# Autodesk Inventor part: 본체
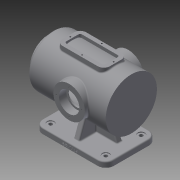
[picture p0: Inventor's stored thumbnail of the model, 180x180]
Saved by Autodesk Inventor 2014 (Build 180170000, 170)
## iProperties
Created: 2021-11
Part Number: 본체
Material: Generic
Document SubType Name: Modeling
Designer: kb542
Density: 1 g/cm^3
Appearance: Default
Author: kb542
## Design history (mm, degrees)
sketch "스케치1"
  geometry: L1 (0, 0)-(210, 0); L2 (0, 32.5)-(0, 47.5); L3 (0, 47.5)-(10, 47.5); L4 (10, 47.5)-(10, 65); L5 (10, 65)-(210, 65); L6 (210, 65)-(210, 0); L7 (0, 32.5)-(25, 32.5); L8 (25, 32.5)-(25, 55); L9 (25, 55)-(200, 55); L10 (200, 55)-(200, 0)
  constraints: 20 end point, 5 perpendicular, 3 parallel, 2 horizontal, 1 point on line, 1 vertical alignment
  dimensions: "d0" = 10 distance between parallel lines of L6 L10; "d1" = 210 distance of L1.start L1.end; "d2" = 25 distance of L2.start L7.end; "d3" = 10 distance of L2.end L3.end; "d4" = 65 diameter of L7 L1; "d5" = 95 diameter of L3 L1; "d6" = 130 diameter of L5 L1; "d7" = 110 diameter of L9 L1
revolve "회전1" sketch "스케치1" stored, may be unused: angle "d8" = 90 deg
node "작업 평면1"
sketch "스케치2"
  geometry: L1 (50, 65)-(190, 65); L2 (210, 45)-(210, -45); L3 (190, -65)-(50, -65); L4 (30, -45)-(30, 45); L5 (0, -47.5)-(0, 47.5) reference; A1 r 20 centre (50, 45) between (50, 65) and (30, 45); A2 r 20 centre (190, 45) between (210, 45) and (190, 65); A3 r 20 centre (190, -45) between (190, -65) and (210, -45); A4 r 20 centre (50, -45) between (30, -45) and (50, -65); 6 further points
  constraints: 8 end point, 8 point on circle, 8 tangent, 6 point on line, 4 centre point, 3 equal radius, 2 midpoint, 2 parallel, 1 horizontal, 1 horizontal alignment, 1 perpendicular
  dimensions: "d10" = 180 distance of point (30, 65) point (210, 65); "d11" = 130 distance of point (30, -65) point (30, 65); "d12" = 30 distance between parallel lines of L4 L5; "d13" = 20 radius of A1
extrude "돌출1" join sketch "스케치2" distance "d14" = 14; taper "d15" = 0 deg
sketch "스케치3"
  geometry: A1 r 20 centre (50, 45) between (50, 65) and (30, 45) reference; A2 r 20 centre (50, -45) between (30, -45) and (50, -65) reference; A3 r 20 centre (190, -45) between (190, -65) and (210, -45) reference; A4 r 20 centre (190, 45) between (210, 45) and (190, 65) reference; 5 further points
  constraints: 4 coincident
hole "구멍1" sketch "스케치3" at (50, 45), (190, 45), (190, -45), (50, -45) diameter "d16" = 9; stored, may be unused: countersink angle "d20" = 90 deg, drill point angle "d22" = 118 deg; dims "d17" = 6, "d18" = 18, "d19" = 2, "d21" = 8
node "작업 평면2"
sketch "스케치4"
  geometry: L1 (65, 30)-(155, 30); L2 (170, 15)-(170, -15); L3 (155, -30)-(65, -30); L4 (50, -15)-(50, 15); L5 (0, -47.5)-(0, 47.5) reference; L6 (155, 20)-(65, 20); L7 (60, 15)-(60, -15); L8 (65, -20)-(155, -20); L9 (160, -15)-(160, 15); A1 r 15 centre (65, 15) between (65, 30) and (50, 15); A2 r 15 centre (65, -15) between (50, -15) and (65, -30); A3 r 15 centre (155, -15) between (155, -30) and (170, -15); A4 r 15 centre (155, 15) between (170, 15) and (155, 30); A5 r 5 centre (65, 15) between (65, 20) and (60, 15); A6 r 5 centre (65, -15) between (60, -15) and (65, -20); A7 r 5 centre (155, -15) between (155, -20) and (160, -15); A8 r 5 centre (155, 15) between (160, 15) and (155, 20); 6 further points
  constraints: 16 end point, 16 point on circle, 8 centre point, 8 tangent, 6 point on line, 4 parallel, 3 equal radius, 2 midpoint, 2 perpendicular, 1 horizontal, 1 horizontal alignment, 7 other
  dimensions: "d24" = 120 distance of point (50, 30) point (170, 30); "d25" = 60 distance of point (50, -30) point (50, 30); "d26" = 50 distance between parallel lines of L5 L4; "d27" = 15 radius of A1; "d28" = 10 distance between parallel lines of L6 L1
extrude "돌출2" join sketch "스케치4" stored distance "d29" = 140; taper "d30" = 0 deg
node "작업 평면3"
sketch "스케치5"
  geometry: L1 (-14, 90)-(-14, 0) reference; L2 (-14, -9)-(-14, 9) reference; L3 (-14, 81)-(-14, 99) reference; L4 (-14, 110)-(-14, 90) reference; L5 (-14, 0)-(-14, -20) reference; L6 (-58.485, 11.191)-(-14, -5); L7 (-58.485, 78.809)-(-14, 95); L8 (-114, 45)-(-49, 45); A1 r 65 centre (-114, 45) between (-58.485, 11.191) and (-58.485, 78.809) reference; 1 further point
  constraints: 6 end point, 3 point on circle, 2 point on line, 1 perpendicular, 1 other
  dimensions: "d31" = 110 deg angle of L5 L6; "d32" = 100 distance of L7.end L6.end
extrude "돌출3" join sketch "스케치5" stored distance "d33" = 14; taper "d34" = 0 deg
node "작업 평면4"
sketch "스케치6"
  geometry: L1 (18.887, 38.416)-(10, 14); L2 (118.776, 44.837)-(130, 14); L3 (140, 14)-(0, 14) reference; L4 (0, 0)-(140, 0) reference; L5 (70, 14)-(70, 0); 1 further point
  constraints: 6 end point, 2 midpoint, 2 point on line, 1 other
  dimensions: "d35" = 110 deg angle of L3 L1; "d37" = 120 distance of L2.end L1.end
feature "리브1" dims "d38" = 1, "d39" = 14, "d40" = 0, "d41" = 0, "d42" = 1, "d43" = 1
feature "리브2" dims "d44" = 1, "d45" = 14, "d46" = 0, "d47" = 0, "d48" = 1, "d49" = 1
node "작업 평면5"
sketch "스케치8"
  geometry: L1 (0, -47.5)-(0, 47.5) reference; C1 r 40 at (127, 0); 2 further points
  constraints: 1 centre point, 1 horizontal alignment, 1 midpoint
  dimensions: "d51" = 127 distance from line of C1.centre L1; "d52" = 80 diameter of C1
extrude "돌출4" join sketch "스케치8" stored distance "d53" = 14; taper "d54" = 0 deg
sketch "스케치9"
  geometry: C1 r 40 at (0, 0) reference; 2 further points
  constraints: 1 coincident
hole "구멍2" sketch "스케치9" at (0, 0) diameter "d55" = 42; stored, may be unused: countersink angle "d59" = 90 deg, drill point angle "d61" = 118 deg; dims "d56" = 6, "d57" = 52, "d58" = 19, "d60" = 8
sketch "스케치10"
  geometry: C1 r 40 at (0, 0) reference; A1 r 32.5 centre (0, 0) between (0, 32.5) and (-32.5, 0); 3 further points
  constraints: 4 point on circle, 1 centre point, 1 coincident
  dimensions: "d62" = 65 diameter of A1
hole "구멍3" sketch "스케치10" at (0, 32.5), (-32.5, 0), (0, -32.5), (32.5, 0) diameter "d63" = 3.242; stored, may be unused: countersink angle "d67" = 90 deg, drill point angle "d69" = 118 deg; dims "d64" = 11, "d65" = 52, "d66" = 19, "d68" = 13
sketch "스케치11"
  geometry: C1 r 32.5 at (0, 0) reference; A1 r 40 centre (0, 0) between (-40, 0) and (0, 40); 2 further points
  constraints: 4 point on circle, 1 centre point, 1 coincident
  dimensions: "d70" = 80 diameter of A1
hole "구멍4" sketch "스케치11" at (-40, 0), (0, 40), (40, 0), (0, -40) diameter "d71" = 3.242; stored, may be unused: countersink angle "d75" = 90 deg, drill point angle "d77" = 118 deg; dims "d72" = 11, "d73" = 52, "d74" = 19, "d76" = 13
sketch "스케치12"
  geometry: L1 (155, -30)-(65, -30) reference; L2 (60, -15)-(60, 15) reference; L3 (65, 20)-(155, 20) reference; L4 (160, 15)-(160, -15) reference; L5 (110, 25)-(110, -25); 10 further points
  constraints: 5 midpoint, 3 horizontal alignment, 2 coincident, 2 end point, 1 perpendicular, 1 vertical alignment
  dimensions: "d78" = 50 distance of L5.start L5.end; "d79" = 55 distance of point (110, 0) point (55, 0); "d80" = 55 distance of point (110, 0) point (165, 0)
hole "구멍5" sketch "스케치12" at (55, 0), (165, 0), (110, 25), (110, -25) diameter "d81" = 3.242; stored, may be unused: countersink angle "d85" = 90 deg, drill point angle "d87" = 118 deg; dims "d82" = 9, "d83" = 52, "d84" = 19, "d86" = 11
fillet "모깎기1" dims "d88" = 3
fillet "모깎기2" dims "d89" = 3
fillet "모깎기3" dims "d90" = 10
chamfer "모따기1" distance "d91" = 1; stored, may be unused: second distance "d92" = 2, angle "d93" = 45 deg
fillet "모깎기4" dims "d94" = 3
sketch "스케치13"
  geometry: L1 (140, 0)-(0, 0) reference; 3 further points
  constraints: 1 midpoint, 1 vertical alignment, 1 other
  dimensions: "d95" = 5 distance from line of L1 point (70, 5)
feature "엠보싱1" sketch "스케치13" dims "d96" = 0.5, "d97" = 0
node "솔리드1"
mirror "대칭1"
other parameters: "d9" = -114, "d50" = -75
